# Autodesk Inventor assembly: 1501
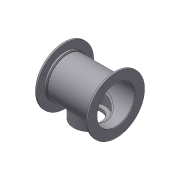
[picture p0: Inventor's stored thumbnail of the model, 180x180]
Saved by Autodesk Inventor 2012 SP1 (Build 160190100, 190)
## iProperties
Created: 2012-02
Part Number: 1501
Document SubType Name: Weldment
Designer: LACO
Weld Material: Welded Aluminum-6061
Mass: 2278.15 g
Surface Area: 3417.52 cm^2
Volume: 840.644 cm^3
Density: 2.71 g/cm^3
Author: LACO
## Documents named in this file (4)
- C:\Documents and Settings\LACO\My Documents\Inventor\rainbow-camera-mount\02 parts\1501.iam
- C:\Documents and Settings\LACO\My Documents\Inventor\rainbow-camera-mount\02 parts\1500.ipt
- C:\Documents and Settings\LACO\My Documents\Inventor\rainbow-camera-mount\02 parts\1504.ipt
- C:\Documents and Settings\LACO\My Documents\Inventor\rainbow-camera-mount\02 parts\1516.ipt
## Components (4 placed, 3 different names)
1. 1500:1 — Insert:1, Insert:3, Mate:2, Mate:3
2. 1504:1 — Insert:1, Mate:1
3. 1504:2 — Insert:3, Mate:1
4. 1516:1 — Mate:2, Mate:3
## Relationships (5: Mate 3, Insert 2)
- Insert:1: 1500:1 ↔ 1504:1
- Insert:3: 1500:1 ↔ 1504:2
- Mate:1: 1504:1 ↔ 1504:2
- Mate:2: 1500:1 ↔ 1516:1
- Mate:3: 1500:1 ↔ 1516:1
